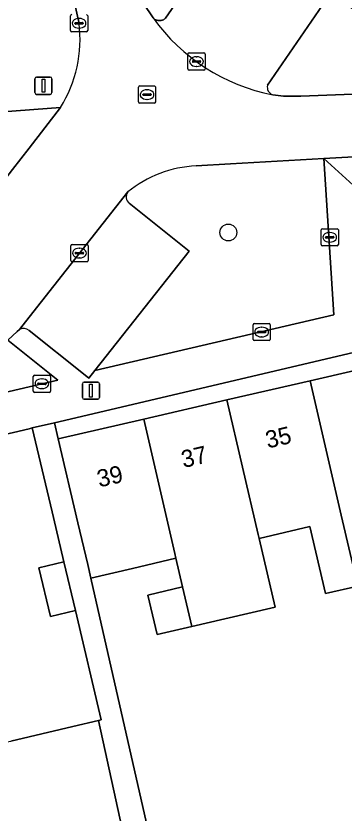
# Model space of a CAD drawing. Extents: x 160856 to 161310, y 384024 to 384878.
# Drawn here: x 160999.24 to 161018.24, y 384674.04 to 384720.28 of the extents above; entities that cross this region are included whole.
import ezdxf

# ---------------------------------------------------------------- set-up
doc = ezdxf.new("R2010")
doc.units = 0
for name, color, linetype in [('IMGEO_Boom', 7, 'Continuous'), ('IMGEO_Erf', 7, 'Continuous'), ('IMGEO_Groenvoorziening', 7, 'Continuous'), ('IMGEO_Kolk', 7, 'Continuous'), ('IMGEO_Lichtmast', 7, 'Continuous'), ('IMGEO_Pand', 7, 'Continuous'), ('IMGEO_Pand_nummerreeks', 7, 'Continuous'), ('IMGEO_Parkeervlak_open', 7, 'Continuous'), ('IMGEO_Rijbaan_lokaal_open', 7, 'Continuous'), ('IMGEO_Rioolput', 7, 'Continuous'), ('IMGEO_Voetpad_open', 7, 'Continuous')]:
    doc.layers.add(name, color=color, linetype=linetype)

msp = doc.modelspace()

# ---------------------------------------------------------------- linework, layer by layer
at = {"layer": 'IMGEO_Boom'}
msp.add_circle((161011.544, 384707.719), 0.489, dxfattribs=at)
at = {"layer": 'IMGEO_Erf'}
for points in [[(161020.098, 384701.072), (161001.472, 384696.684), (161001.694, 384695.742), (161006.641, 384696.888), (161011.46, 384698.004), (161016.279, 384699.12), (161021.204, 384700.261)], [(161019.037, 384687.212), (161017.177, 384686.777), (161016.27, 384690.656), (161013.321, 384689.966), (161014.25, 384685.993), (161011.333, 384685.311), (161009.425, 384684.865), (161007.417, 384684.395), (161006.881, 384686.686), (161008.894, 384687.157), (161008.509, 384688.823), (161005.999, 384688.235), (161003.583, 384687.669), (161009.497, 384661.544), (161027.455, 384660.754)], [(161007.907, 384661.614), (161004.02, 384679.414), (161002.543, 384679.067), (161000, 384678.469), (160998.938, 384678.218)]]:
    msp.add_lwpolyline(points, dxfattribs=at)
msp.add_lwpolyline([(161002.012, 384688.611), (161000.575, 384688.273), (161001.242, 384685.441), (161002.696, 384685.783)], close=True, dxfattribs=at)
at = {"layer": 'IMGEO_Groenvoorziening'}
for points in [[(161005.803, 384709.414), (161009.282, 384706.645), (161003.807, 384699.717), (161017.659, 384702.946), (161017.08, 384712.007)], [(161017.08, 384712.007), (161011.677, 384711.708), (161009.67, 384711.582)], [(160995.668, 384699.122), (160995.374, 384698.633), (160994.843, 384697.57), (161000, 384698.766), (161001.675, 384699.162), (160998.778, 384701.469)]]:
    msp.add_lwpolyline(points, dxfattribs=at)
for centre, radius, start, end in [((161009.989, 384704.824), 6.765, 92.7034, 129.1598), ((161006.124, 384709.79), 0.494, 145.4216, 229.5159)]:
    msp.add_arc(centre, radius, start, end, dxfattribs=at)
at = {"layer": 'IMGEO_Kolk'}
for p, q in [((161002.395, 384719.428), (161002.395, 384720.28)), ((161002.654, 384719.848), (161002.654, 384719.86)), ((161002.697, 384719.897), (161003.095, 384719.897)), ((161002.883, 384720.134), (161002.908, 384720.134)), ((161003.138, 384719.86), (161003.138, 384719.848)), ((161003.396, 384720.28), (161003.396, 384719.428)), ((161003.092, 384719.811), (161002.694, 384719.811)), ((161002.906, 384719.574), (161002.881, 384719.574)), ((161003.322, 384719.354), (161002.47, 384719.354)), ((161009.2, 384717.209), (161009.2, 384718.061)), ((161009.275, 384718.135), (161010.127, 384718.135)), ((161010.201, 384718.061), (161010.201, 384717.209)), ((161009.459, 384717.629), (161009.459, 384717.641)), ((161009.897, 384717.592), (161009.499, 384717.592)), ((161009.502, 384717.678), (161009.9, 384717.678)), ((161009.688, 384717.915), (161009.713, 384717.915)), ((161009.943, 384717.641), (161009.943, 384717.629)), ((161010.127, 384717.135), (161009.275, 384717.135)), ((161009.711, 384717.355), (161009.686, 384717.355)), ((161016.915, 384707.013), (161016.915, 384707.865)), ((161016.99, 384707.939), (161017.842, 384707.939)), ((161017.916, 384707.865), (161017.916, 384707.013)), ((161017.174, 384707.433), (161017.174, 384707.445)), ((161017.612, 384707.396), (161017.214, 384707.396)), ((161017.217, 384707.482), (161017.615, 384707.482)), ((161017.403, 384707.719), (161017.428, 384707.719)), ((161017.658, 384707.445), (161017.658, 384707.433)), ((161002.419, 384706.098), (161002.419, 384706.95)), ((161002.494, 384707.024), (161003.346, 384707.024)), ((161003.42, 384706.95), (161003.42, 384706.098)), ((161017.842, 384706.939), (161016.99, 384706.939)), ((161017.426, 384707.159), (161017.401, 384707.159)), ((161002.678, 384706.518), (161002.678, 384706.53)), ((161003.116, 384706.481), (161002.718, 384706.481)), ((161002.721, 384706.567), (161003.119, 384706.567)), ((161002.907, 384706.804), (161002.932, 384706.804)), ((161003.162, 384706.53), (161003.162, 384706.518)), ((161003.346, 384706.024), (161002.494, 384706.024)), ((161002.93, 384706.244), (161002.905, 384706.244)), ((161012.972, 384701.519), (161012.972, 384702.371)), ((161013.047, 384702.445), (161013.899, 384702.445)), ((161013.973, 384702.371), (161013.973, 384701.519)), ((161013.231, 384701.939), (161013.231, 384701.951)), ((161013.669, 384701.902), (161013.271, 384701.902)), ((161013.274, 384701.988), (161013.672, 384701.988)), ((161013.46, 384702.225), (161013.485, 384702.225)), ((161013.715, 384701.951), (161013.715, 384701.939)), ((161013.899, 384701.445), (161013.047, 384701.445)), ((161013.483, 384701.665), (161013.458, 384701.665)), ((161000.245, 384698.518), (161000.245, 384699.37)), ((161000.32, 384699.444), (161001.172, 384699.444)), ((161000.733, 384699.224), (161000.758, 384699.224)), ((161001.246, 384699.37), (161001.246, 384698.518)), ((161000.504, 384698.938), (161000.504, 384698.95)), ((161000.942, 384698.901), (161000.544, 384698.901)), ((161000.547, 384698.987), (161000.945, 384698.987)), ((161000.756, 384698.664), (161000.731, 384698.664)), ((161000.988, 384698.95), (161000.988, 384698.938)), ((161001.172, 384698.444), (161000.32, 384698.444))]:
    msp.add_line(p, q, dxfattribs=at)
for points in [[(161002.395, 384719.428), (161002.395, 384720.28)], [(161003.396, 384720.28), (161003.396, 384719.428)], [(161003.322, 384719.354), (161002.47, 384719.354)], [(161009.2, 384717.209), (161009.2, 384718.061)], [(161009.275, 384718.135), (161010.127, 384718.135)], [(161010.201, 384718.061), (161010.201, 384717.209)], [(161010.127, 384717.135), (161009.275, 384717.135)], [(161016.915, 384707.013), (161016.915, 384707.865)], [(161016.99, 384707.939), (161017.842, 384707.939)], [(161017.916, 384707.865), (161017.916, 384707.013)], [(161002.419, 384706.098), (161002.419, 384706.95)], [(161002.494, 384707.024), (161003.346, 384707.024)], [(161003.42, 384706.95), (161003.42, 384706.098)], [(161017.842, 384706.939), (161016.99, 384706.939)], [(161003.346, 384706.024), (161002.494, 384706.024)], [(161012.972, 384701.519), (161012.972, 384702.371)], [(161013.047, 384702.445), (161013.899, 384702.445)], [(161013.973, 384702.371), (161013.973, 384701.519)], [(161013.899, 384701.445), (161013.047, 384701.445)], [(161000.245, 384698.518), (161000.245, 384699.37)], [(161000.32, 384699.444), (161001.172, 384699.444)], [(161001.246, 384699.37), (161001.246, 384698.518)], [(161001.172, 384698.444), (161000.32, 384698.444)]]:
    msp.add_lwpolyline(points, dxfattribs=at)
for centre, radius, start, end in [((161002.472, 384720.278), 0.0765, 91.552, 178.448), ((161002.472, 384720.278), 0.0765, 91.552, 178.448), ((161003.32, 384720.278), 0.0765, 1.552, 88.448), ((161003.32, 384720.278), 0.0765, 1.552, 88.448), ((161002.694, 384719.857), 0.0403, 85.8775, 175.7526), ((161002.691, 384719.847), 0.0366, 178.938, 274.7102), ((161003.095, 384719.854), 0.043, 264.8664, 352.4533), ((161003.099, 384719.859), 0.0386, 1.7309, 96.639), ((161002.472, 384719.43), 0.0765, 181.552, 268.448), ((161002.472, 384719.43), 0.0765, 181.552, 268.448), ((161003.32, 384719.43), 0.0765, 271.552, 358.448), ((161003.32, 384719.43), 0.0765, 271.552, 358.448), ((161009.277, 384718.059), 0.0765, 91.552, 178.448), ((161009.277, 384718.059), 0.0765, 91.552, 178.448), ((161010.125, 384718.059), 0.0765, 1.552, 88.448), ((161010.125, 384718.059), 0.0765, 1.552, 88.448), ((161009.499, 384717.638), 0.0403, 85.8775, 175.7526), ((161009.496, 384717.628), 0.0366, 178.938, 274.7102), ((161009.9, 384717.635), 0.043, 264.8664, 352.4533), ((161009.904, 384717.64), 0.0386, 1.7309, 96.639), ((161009.277, 384717.211), 0.0765, 181.552, 268.448), ((161009.277, 384717.211), 0.0765, 181.552, 268.448), ((161010.125, 384717.211), 0.0765, 271.552, 358.448), ((161010.125, 384717.211), 0.0765, 271.552, 358.448), ((161016.992, 384707.863), 0.0765, 91.552, 178.448), ((161016.992, 384707.863), 0.0765, 91.552, 178.448), ((161017.84, 384707.863), 0.0765, 1.552, 88.448), ((161017.84, 384707.863), 0.0765, 1.552, 88.448), ((161017.214, 384707.442), 0.0403, 85.8775, 175.7526), ((161017.211, 384707.432), 0.0366, 178.938, 274.7102), ((161017.615, 384707.439), 0.043, 264.8664, 352.4533), ((161017.619, 384707.444), 0.0386, 1.7309, 96.639), ((161002.496, 384706.948), 0.0765, 91.552, 178.448), ((161002.496, 384706.948), 0.0765, 91.552, 178.448), ((161003.344, 384706.948), 0.0765, 1.552, 88.448), ((161003.344, 384706.948), 0.0765, 1.552, 88.448), ((161016.992, 384707.015), 0.0765, 181.552, 268.448), ((161016.992, 384707.015), 0.0765, 181.552, 268.448), ((161017.84, 384707.015), 0.0765, 271.552, 358.448), ((161017.84, 384707.015), 0.0765, 271.552, 358.448), ((161002.718, 384706.527), 0.0403, 85.8775, 175.7526), ((161002.715, 384706.517), 0.0366, 178.938, 274.7102), ((161003.119, 384706.524), 0.043, 264.8664, 352.4533), ((161003.123, 384706.529), 0.0386, 1.7309, 96.639), ((161002.496, 384706.1), 0.0765, 181.552, 268.448), ((161002.496, 384706.1), 0.0765, 181.552, 268.448), ((161003.344, 384706.1), 0.0765, 271.552, 358.448), ((161003.344, 384706.1), 0.0765, 271.552, 358.448), ((161013.049, 384702.369), 0.0765, 91.552, 178.448), ((161013.049, 384702.369), 0.0765, 91.552, 178.448), ((161013.897, 384702.369), 0.0765, 1.552, 88.448), ((161013.897, 384702.369), 0.0765, 1.552, 88.448), ((161013.271, 384701.948), 0.0403, 85.8775, 175.7526), ((161013.268, 384701.938), 0.0366, 178.938, 274.7102), ((161013.672, 384701.945), 0.043, 264.8664, 352.4533), ((161013.676, 384701.95), 0.0386, 1.7309, 96.639), ((161013.049, 384701.521), 0.0765, 181.552, 268.448), ((161013.049, 384701.521), 0.0765, 181.552, 268.448), ((161013.897, 384701.521), 0.0765, 271.552, 358.448), ((161013.897, 384701.521), 0.0765, 271.552, 358.448), ((161000.322, 384699.368), 0.0765, 91.552, 178.448), ((161000.322, 384699.368), 0.0765, 91.552, 178.448), ((161001.17, 384699.368), 0.0765, 1.552, 88.448), ((161001.17, 384699.368), 0.0765, 1.552, 88.448), ((161000.544, 384698.947), 0.0403, 85.8775, 175.7526), ((161000.541, 384698.937), 0.0366, 178.938, 274.7102), ((161000.945, 384698.944), 0.043, 264.8664, 352.4533), ((161000.949, 384698.949), 0.0386, 1.7309, 96.639), ((161000.322, 384698.52), 0.0765, 181.552, 268.448), ((161000.322, 384698.52), 0.0765, 181.552, 268.448), ((161001.17, 384698.52), 0.0765, 271.552, 358.448), ((161001.17, 384698.52), 0.0765, 271.552, 358.448)]:
    msp.add_arc(centre, radius, start, end, dxfattribs=at)
for centre, major_axis, ratio, start_param, end_param in [((161002.882, 384719.854), (-0.387, 0.002), 0.722429, 4.712389, 7.853982), ((161002.907, 384719.854), (-0.39, 0.002), 0.717154, 1.570796, 4.712389), ((161009.687, 384717.635), (-0.387, 0.002), 0.722429, 4.712389, 7.853982), ((161009.712, 384717.635), (-0.39, 0.002), 0.717154, 1.570796, 4.712389), ((161017.402, 384707.439), (-0.387, 0.002), 0.722429, 4.712389, 7.853982), ((161017.427, 384707.439), (-0.39, 0.002), 0.717154, 1.570796, 4.712389), ((161002.906, 384706.524), (-0.387, 0.002), 0.722429, 4.712389, 7.853982), ((161002.931, 384706.524), (-0.39, 0.002), 0.717154, 1.570796, 4.712389), ((161013.459, 384701.945), (-0.387, 0.002), 0.722429, 4.712389, 7.853982), ((161013.484, 384701.945), (-0.39, 0.002), 0.717154, 1.570796, 4.712389), ((161000.732, 384698.944), (-0.387, 0.002), 0.722429, 4.712389, 7.853982), ((161000.757, 384698.944), (-0.39, 0.002), 0.717154, 1.570796, 4.712389)]:
    msp.add_ellipse(centre, major_axis=major_axis, ratio=ratio, start_param=start_param, end_param=end_param, dxfattribs=at)
at = {"layer": 'IMGEO_Lichtmast'}
for p, q in [((161000.338, 384715.832), (161000.338, 384716.632)), ((161000.338, 384716.632), (161000.338, 384715.832)), ((161000.438, 384716.732), (161001.228, 384716.732)), ((161001.228, 384716.732), (161000.438, 384716.732)), ((161001.328, 384716.632), (161001.328, 384715.832)), ((161001.328, 384715.832), (161001.328, 384716.632)), ((161001.228, 384715.732), (161000.438, 384715.732)), ((161000.438, 384715.732), (161001.228, 384715.732)), ((161003.189, 384699.042), (161003.979, 384699.042)), ((161003.979, 384699.042), (161003.189, 384699.042)), ((161003.089, 384698.142), (161003.089, 384698.942)), ((161003.089, 384698.942), (161003.089, 384698.142)), ((161004.079, 384698.942), (161004.079, 384698.142)), ((161004.079, 384698.142), (161004.079, 384698.942)), ((161003.979, 384698.042), (161003.189, 384698.042)), ((161003.189, 384698.042), (161003.979, 384698.042))]:
    msp.add_line(p, q, dxfattribs=at)
for points in [[(161000.758, 384716.607), (161000.908, 384716.607), (161000.908, 384715.857), (161000.758, 384715.857), (161000.758, 384716.607)], [(161003.509, 384698.917), (161003.659, 384698.917), (161003.659, 384698.167), (161003.509, 384698.167), (161003.509, 384698.917)]]:
    msp.add_lwpolyline(points, dxfattribs=at)
for centre, start, end in [((161000.438, 384716.632), 90, 180), ((161000.438, 384716.632), 90, 180), ((161001.228, 384716.632), 0, 90), ((161001.228, 384716.632), 360, 90), ((161000.438, 384715.832), 180, 270), ((161000.438, 384715.832), 180, 270), ((161001.228, 384715.832), 270, 0), ((161001.228, 384715.832), 270, 0), ((161003.189, 384698.942), 90, 180), ((161003.189, 384698.942), 90, 180), ((161003.979, 384698.942), 0, 90), ((161003.979, 384698.942), 360, 90), ((161003.189, 384698.142), 180, 270), ((161003.189, 384698.142), 180, 270), ((161003.979, 384698.142), 270, 0), ((161003.979, 384698.142), 270, 0)]:
    msp.add_arc(centre, 0.1, start, end, dxfattribs=at)
at = {"layer": 'IMGEO_Pand'}
for points in [[(161022.343, 384695.393), (161021.204, 384700.261), (161016.279, 384699.12), (161018.084, 384691.326), (161019.037, 384687.212), (161019.271, 384687.267), (161021.153, 384687.708), (161020.234, 384691.638), (161023.066, 384692.301)], [(161019.037, 384687.212), (161018.084, 384691.326), (161016.279, 384699.12), (161011.46, 384698.004), (161013.265, 384690.21), (161013.321, 384689.966), (161016.27, 384690.656), (161017.177, 384686.777)], [(161011.46, 384698.004), (161006.641, 384696.888), (161008.446, 384689.093), (161008.509, 384688.823), (161008.894, 384687.157), (161009.425, 384684.865), (161011.333, 384685.311), (161014.25, 384685.993), (161013.321, 384689.966), (161013.265, 384690.21)], [(161006.641, 384696.888), (161001.694, 384695.742), (161002.833, 384690.874), (161003.397, 384688.464), (161003.583, 384687.669), (161005.999, 384688.235), (161008.509, 384688.823), (161008.446, 384689.093)], [(161000.575, 384688.273), (161002.012, 384688.611), (161001.815, 384689.447), (161001.329, 384691.514), (161000.184, 384696.381), (161000, 384696.338), (160995.201, 384695.209), (160997.049, 384687.351), (160996.704, 384687.269), (160996.648, 384687.069), (160998.171, 384680.595), (160998.741, 384678.172), (160998.938, 384678.218), (161000, 384678.469), (161002.543, 384679.067), (161004.02, 384679.414), (161004.186, 384679.453), (161002.696, 384685.783), (161001.242, 384685.441)], [(161009.425, 384684.865), (161008.894, 384687.157), (161006.881, 384686.686), (161007.417, 384684.395)]]:
    msp.add_lwpolyline(points, close=True, dxfattribs=at)
at = {"layer": 'IMGEO_Parkeervlak_open'}
for points in [[(161013.814, 384716.265), (161017.413, 384721.551), (161011.597, 384725.51), (161007.901, 384720.147), (161007.892, 384720.139), (161007.856, 384720.11), (161007.818, 384720.085), (161007.778, 384720.063), (161007.736, 384720.044), (161007.692, 384720.03), (161007.647, 384720.02), (161007.602, 384720.013), (161007.556, 384720.011), (161007.51, 384720.013), (161007.465, 384720.018), (161007.42, 384720.028), (161007.376, 384720.042), (161007.334, 384720.06), (161007.293, 384720.081), (161007.255, 384720.106), (161007.218, 384720.135), (161007.185, 384720.166)], [(161005.717, 384710.07), (161000, 384702.803), (160999.442, 384702.091)], [(161000, 384702.03), (161003.161, 384699.513), (161003.459, 384699.276), (161003.807, 384699.717), (161009.282, 384706.645), (161005.803, 384709.414)]]:
    msp.add_lwpolyline(points, dxfattribs=at)
for centre, radius, start, end in [((161016.291, 384726.696), 11.206, 215.6427, 258.7899), ((161014.265, 384716.145), 0.467, 165.1115, 251.0017), ((161006.124, 384709.79), 0.494, 145.4216, 229.5159), ((160999.682, 384701.706), 0.454, 45.5845, 121.938)]:
    msp.add_arc(centre, radius, start, end, dxfattribs=at)
at = {"layer": 'IMGEO_Rijbaan_lokaal_open'}
for points in [[(161007.185, 384720.166), (161006.075, 384721.859), (161005.657, 384722.841), (161002.394, 384722.089), (161002.898, 384719.85)], [(161017.08, 384712.007), (161057.268, 384714.228), (161057.163, 384717.812), (161019.194, 384715.67), (161019.231, 384715.788), (161018.755, 384715.743), (161015.733, 384715.62), (161014.728, 384715.629), (161014.113, 384715.704)], [(161001.824, 384714.974), (161000, 384712.619), (160999.036, 384711.374), (160995.811, 384707.21), (160994.23, 384705.618)], [(161009.67, 384711.582), (161011.677, 384711.708), (161017.08, 384712.007)], [(160996.44, 384699.783), (160997.347, 384700.315), (160998.129, 384700.872), (160998.778, 384701.469), (160999.318, 384701.967), (160999.442, 384702.091), (161000, 384702.803), (161005.717, 384710.07)]]:
    msp.add_lwpolyline(points, dxfattribs=at)
for centre, radius, start, end in [((160995.497, 384718.924), 7.459, 328.0245, 7.132), ((161016.291, 384726.696), 11.206, 215.6427, 258.7899), ((161009.989, 384704.824), 6.765, 92.7034, 129.1598)]:
    msp.add_arc(centre, radius, start, end, dxfattribs=at)
at = {"layer": 'IMGEO_Rioolput'}
for p, q in [((161006.332, 384715.291), (161006.332, 384716.143)), ((161006.407, 384716.217), (161007.259, 384716.217)), ((161007.333, 384716.143), (161007.333, 384715.291)), ((161006.591, 384715.711), (161006.591, 384715.723)), ((161007.029, 384715.674), (161006.631, 384715.674)), ((161006.634, 384715.76), (161007.032, 384715.76)), ((161006.82, 384715.997), (161006.845, 384715.997)), ((161007.075, 384715.723), (161007.075, 384715.711)), ((161007.259, 384715.217), (161006.407, 384715.217)), ((161006.843, 384715.437), (161006.818, 384715.437))]:
    msp.add_line(p, q, dxfattribs=at)
for points in [[(161006.332, 384715.291), (161006.332, 384716.143)], [(161006.407, 384716.217), (161007.259, 384716.217)], [(161007.333, 384716.143), (161007.333, 384715.291)], [(161007.259, 384715.217), (161006.407, 384715.217)]]:
    msp.add_lwpolyline(points, dxfattribs=at)
for centre, radius, start, end in [((161006.409, 384716.141), 0.0765, 91.552, 178.448), ((161006.409, 384716.141), 0.0765, 91.552, 178.448), ((161007.257, 384716.141), 0.0765, 1.552, 88.448), ((161007.257, 384716.141), 0.0765, 1.552, 88.448), ((161006.631, 384715.72), 0.0403, 85.8775, 175.7526), ((161006.628, 384715.71), 0.0366, 178.938, 274.7102), ((161007.032, 384715.717), 0.043, 264.8664, 352.4533), ((161007.036, 384715.722), 0.0386, 1.7309, 96.639), ((161006.409, 384715.293), 0.0765, 181.552, 268.448), ((161006.409, 384715.293), 0.0765, 181.552, 268.448), ((161007.257, 384715.293), 0.0765, 271.552, 358.448), ((161007.257, 384715.293), 0.0765, 271.552, 358.448)]:
    msp.add_arc(centre, radius, start, end, dxfattribs=at)
for centre, major_axis, ratio, start_param, end_param in [((161006.819, 384715.717), (-0.387, 0.002), 0.722429, 4.712389, 7.853982), ((161006.844, 384715.717), (-0.39, 0.002), 0.717154, 1.570796, 4.712389)]:
    msp.add_ellipse(centre, major_axis=major_axis, ratio=ratio, start_param=start_param, end_param=end_param, dxfattribs=at)
at = {"layer": 'IMGEO_Voetpad_open'}
for points in [[(160975.504, 384842.631), (160975.364, 384843.569), (160974.84, 384846.396), (160973.754, 384851.919), (160973.549, 384852.917), (160970.553, 384852.358), (160975.639, 384823.391), (160980.654, 384801.69), (160980.906, 384800.6), (160992.6, 384750), (160996.597, 384732.705), (160996.604, 384732.664), (160996.834, 384731.34), (160997.799, 384725.788), (160998.487, 384714.721), (161001.824, 384714.974)], [(161002.898, 384719.85), (161002.394, 384722.089), (161001.801, 384724.723), (161001.43, 384726.368), (161001.366, 384726.644)], [(161006.075, 384721.859), (161007.185, 384720.166), (161007.218, 384720.135), (161007.255, 384720.106), (161007.293, 384720.081), (161007.334, 384720.06), (161007.376, 384720.042), (161007.42, 384720.028), (161007.465, 384720.018), (161007.51, 384720.013), (161007.556, 384720.011), (161007.602, 384720.013), (161007.647, 384720.02), (161007.692, 384720.03), (161007.736, 384720.044), (161007.778, 384720.063), (161007.818, 384720.085), (161007.856, 384720.11), (161007.892, 384720.139), (161007.901, 384720.147), (161011.597, 384725.51)], [(161061.194, 384719.726), (161061.537, 384720.135), (161061.842, 384720.573), (161062.107, 384721.037), (161062.329, 384721.523), (161062.508, 384722.027), (161059.302, 384721.83), (161018.927, 384719.697), (161018.857, 384720.62), (161017.413, 384721.551), (161013.814, 384716.265)], [(161014.113, 384715.704), (161014.728, 384715.629), (161015.733, 384715.62), (161018.755, 384715.743), (161019.231, 384715.788)], [(160994.23, 384705.618), (160995.811, 384707.21), (160999.036, 384711.374), (161000, 384712.619), (161001.824, 384714.974), (160998.487, 384714.721), (160996.631, 384712.258), (160990.485, 384704.401), (160980.053, 384702.083), (160979.817, 384703.005), (160978.712, 384702.734), (160978.898, 384701.99), (160976.207, 384701.405), (160976.168, 384701.622), (160972.317, 384700.651), (160965.811, 384699.01), (160962.66, 384698.215), (160962.721, 384697.973), (160954.629, 384694.918), (160948.331, 384692.54), (160925.586, 384683.954), (160926.724, 384680.788), (160927.644, 384681.106), (160928.722, 384681.501)], [(160981.722, 384692.037), (160988.461, 384693.623), (160995.201, 384695.209), (161000, 384696.338), (161000.184, 384696.381), (161001.472, 384696.684), (161020.098, 384701.072), (161019.614, 384709.69), (161017.08, 384712.007), (161017.659, 384702.946), (161003.807, 384699.717), (161003.459, 384699.276), (161003.161, 384699.513), (161000, 384702.03)], [(160999.442, 384702.091), (160999.318, 384701.967), (160998.778, 384701.469), (161001.675, 384699.162), (161000, 384698.766), (160994.843, 384697.57), (160994.506, 384696.895)], [(161009.497, 384661.544), (161003.583, 384687.669), (161003.397, 384688.464), (161002.833, 384690.874), (161001.694, 384695.742), (161001.472, 384696.684), (161000.184, 384696.381), (161001.329, 384691.514), (161001.815, 384689.447), (161002.012, 384688.611), (161002.696, 384685.783), (161004.186, 384679.453), (161004.02, 384679.414), (161007.907, 384661.614)]]:
    msp.add_lwpolyline(points, dxfattribs=at)
msp.add_lwpolyline([(161102.199, 384714.46), (161103.389, 384714.53), (161107.975, 384714.798), (161108.062, 384716.536), (161101.991, 384716.2), (161101.964, 384716.699), (161072.03, 384715.044), (161057.268, 384714.228), (161017.08, 384712.007), (161019.614, 384709.69), (161049.56, 384711.368), (161050.754, 384711.435), (161062.499, 384712.093), (161068.593, 384712.435), (161080.748, 384713.117), (161081.846, 384713.178), (161096.723, 384713.991), (161097.096, 384707.169), (161099.448, 384706.782), (161101.13, 384709.076), (161099.19, 384710.395)], close=True, dxfattribs=at)
for centre, radius, start, end in [((160995.497, 384718.924), 7.459, 328.0245, 7.132), ((161014.265, 384716.145), 0.467, 165.1115, 251.0017), ((160999.682, 384701.706), 0.454, 45.5845, 121.938)]:
    msp.add_arc(centre, radius, start, end, dxfattribs=at)

# ---------------------------------------------------------------- texts
at = {"layer": 'IMGEO_Pand_nummerreeks'}
for s, p in [('35', (161013.822, 384695.185)), ('37', (161008.945, 384694.055)), ('39', (161004.067, 384692.926))]:
    msp.add_text(s, height=1, rotation=13.0412, dxfattribs=at).set_placement(p)

doc.saveas('drawing.dxf')
